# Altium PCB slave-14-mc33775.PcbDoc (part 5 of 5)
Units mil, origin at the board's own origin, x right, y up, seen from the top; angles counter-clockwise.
Board outline 6299.21 x 3937.01 mil, 6 copper layers (Top Copper, Supply, Signal Layer 1, Signal Layer 2, GND, Bot Copper), stack 69.773 mil thick; 428 components, 213 nets, 1149 pads, 1672 vias.
Unrouted connection lines stored in the file: 1.
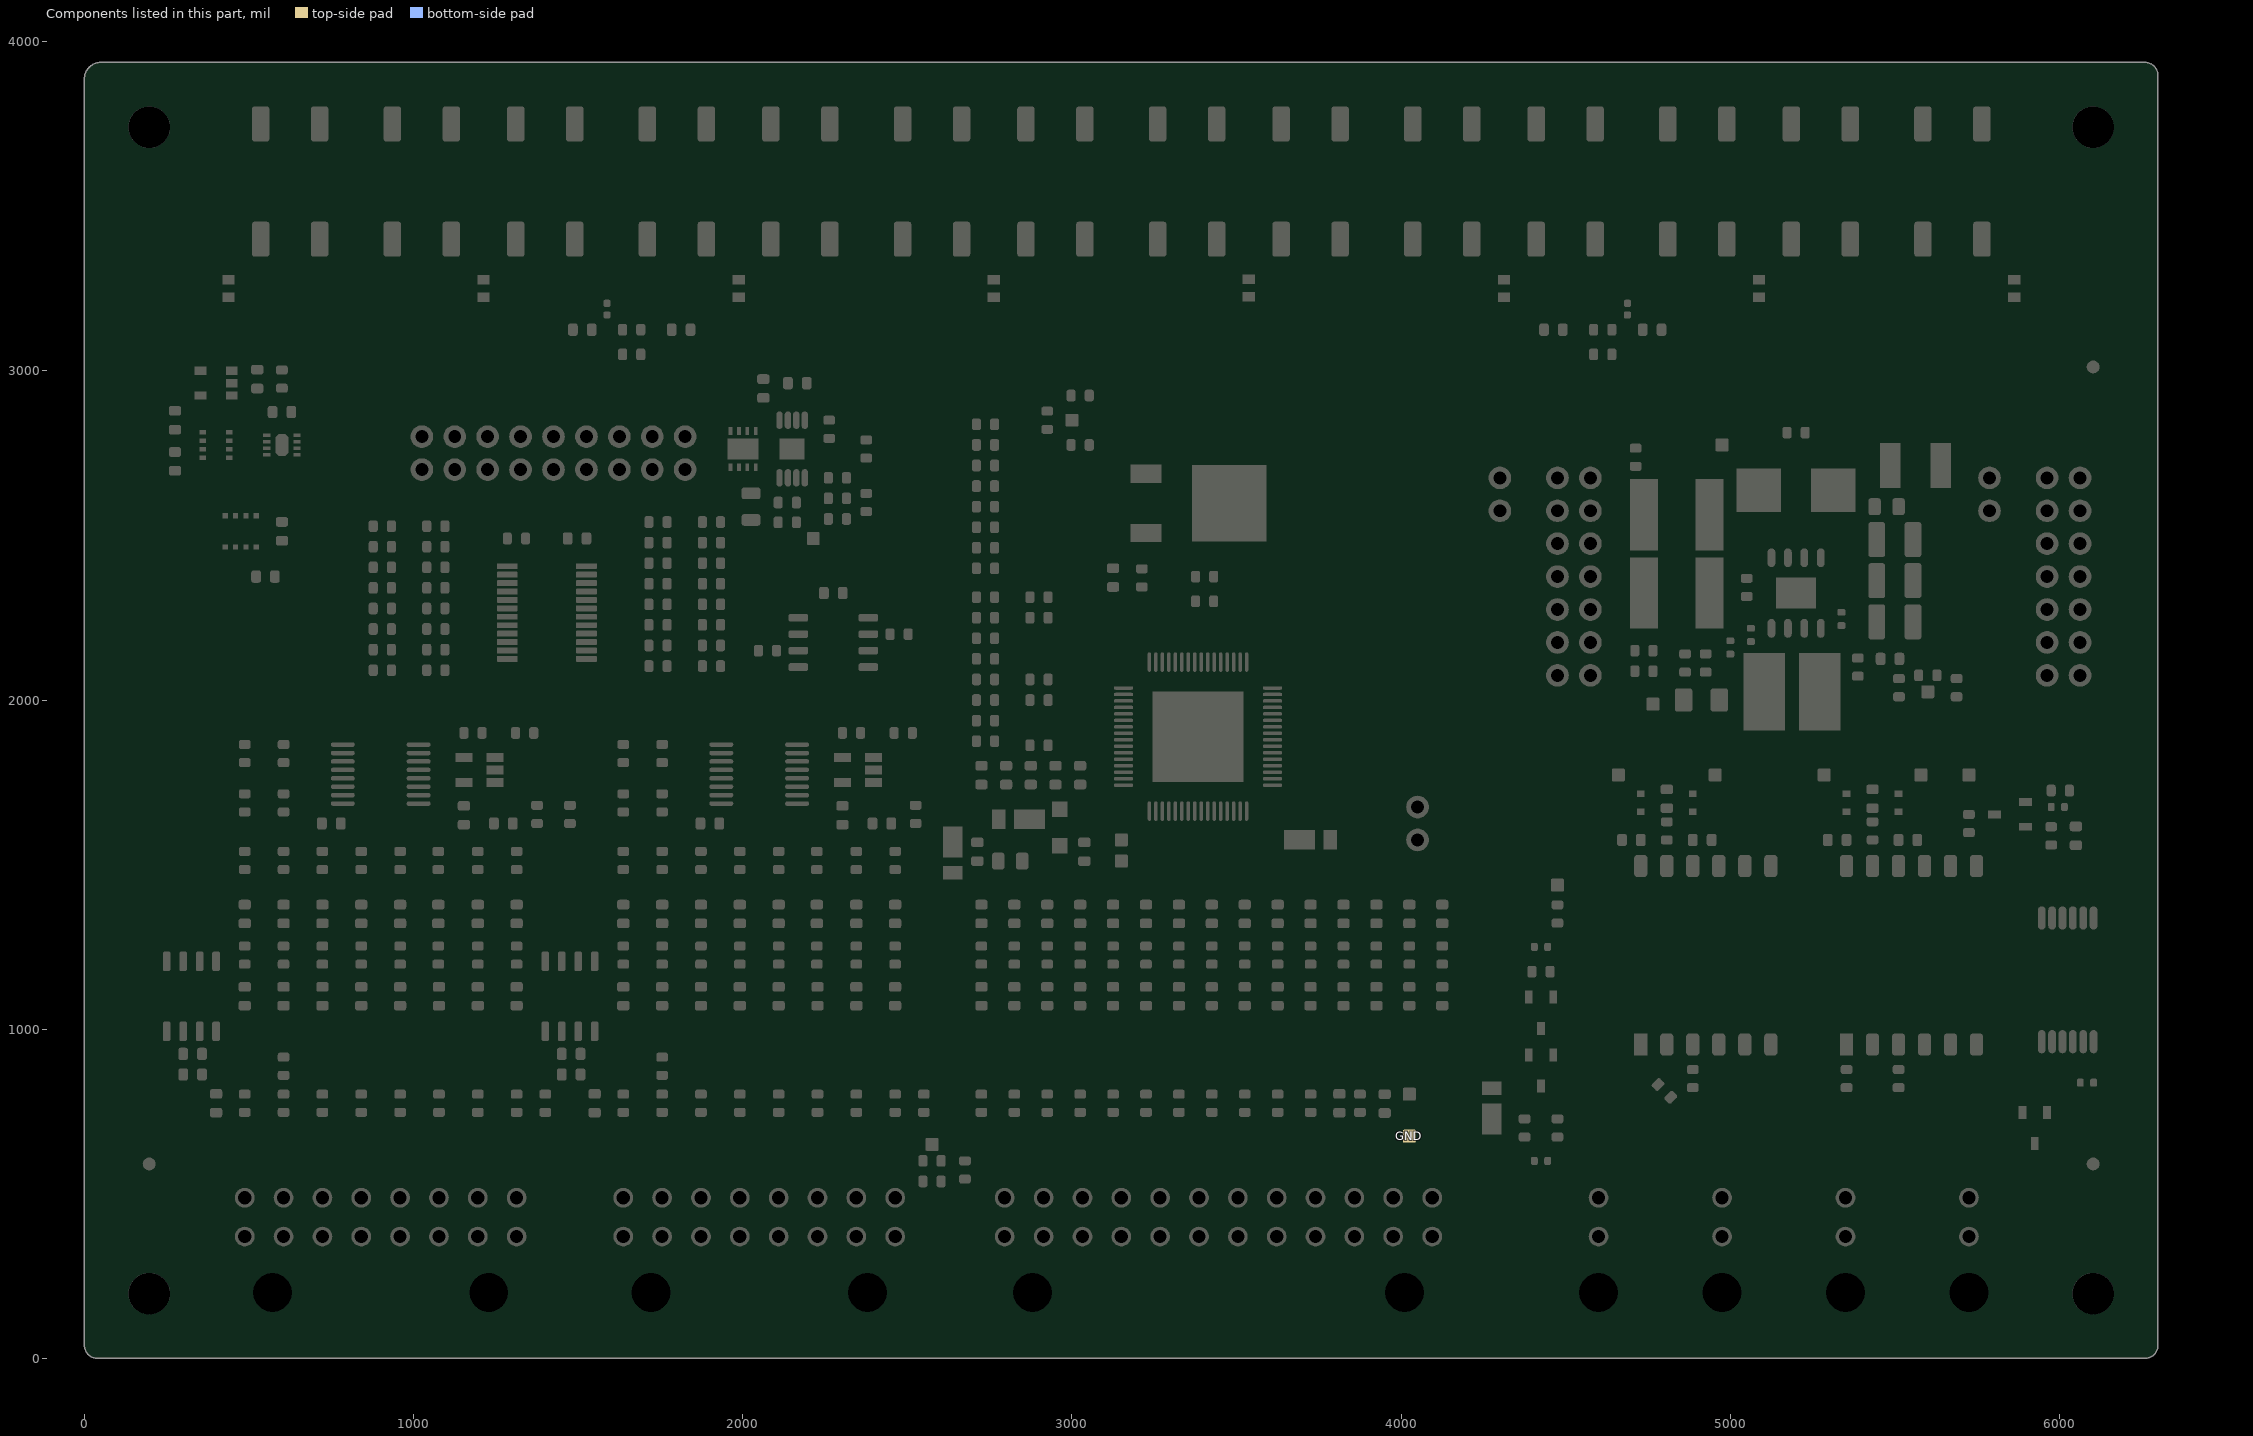
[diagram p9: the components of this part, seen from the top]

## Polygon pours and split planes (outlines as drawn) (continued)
no net on Top Overlay "Polygon_24_NoNet" (solid): 5467.42,2986.05 5468.17,2982.8 5470.88,2981.57 5473.58,2982.8 5474.34,2986.06 5474.34,3047.53 5498.56,2996.96 5500.45,2994.13 5503.43,2993.08 5506.4,2994.13 5508.29,2996.96 5532.51,3047.53 5532.51,2986.06 5533.27,2982.8 5535.97,2981.57 5538.69,2982.8 5539.44,2986.06 5539.44,3059.6 5539.13,3061.72 5538.22,3063.07 5535.75,3064.03 5533.45,3063.42 5531.48,3060.72 5503.43,3001.37 5475.39,3060.72 5473.42,3063.42 5471.12,3064.03 5468.65,3063.07 5467.74,3061.72 5467.43,3059.6 5467.41,2986.77 5467.4,2986.25
no net on Top Overlay "Polygon_22_NoNet" (solid): 5660.93,3062.77 5664.56,3062.13 5667.31,3060.36 5669.08,3057.62 5669.71,3054.03 5669.71,2991.35 5669.08,2987.72 5667.31,2984.98 5664.56,2983.21 5660.93,2982.57 5653.92,2981.15 5648.14,2977.25 5644.24,2971.48 5642.81,2964.45 5642.81,2951.01 5642.05,2947.42 5640.08,2944.66 5637.28,2942.89 5634.07,2942.26 5388.97,2942.26 5388.16,2932.83 5634.09,2932.83 5637.72,2933.2 5641.12,2934.27 5644.21,2935.95 5646.9,2938.17 5649.13,2940.86 5650.8,2943.94 5651.86,2947.34 5652.24,2950.98 5652.23,2964.39 5652.87,2968.02 5654.64,2970.76 5657.38,2972.53 5661,2973.16 5664.63,2973.53 5668.02,2974.6 5671.11,2976.27 5673.8,2978.49 5676.02,2981.18 5677.69,2984.26 5678.76,2987.66 5679.13,2991.3 5679.13,3054.05 5678.77,3057.73 5677.73,3061.17 5676.08,3064.26 5673.88,3066.92 5671.2,3069.13 5668.11,3070.78 5664.68,3071.81 5661.02,3072.17 5657.39,3072.85 5654.64,3074.7 5652.87,3077.48 5652.24,3080.91 5652.24,3094.36 5651.87,3097.99 5650.8,3101.4 5649.13,3104.49 5646.9,3107.18 5644.21,3109.39 5641.12,3111.07 5637.72,3112.13 5634.09,3112.5 5140.91,3112.5 5136.76,3112.17 5133.11,3111.2 5129.99,3109.63 5127.41,3107.5 5125.39,3104.86 5123.93,3101.76 5123.05,3098.24 5122.75,3094.36 5122.75,2950.98 5123.12,2947.34 5124.18,2943.94 5125.87,2940.86 5128.09,2938.17 5130.78,2935.95 5133.86,2934.27 5137.27,2933.2 5140.91,2932.83 5388.16,2932.83 5388.97,2942.26 5140.95,2942.25 5137.33,2942.89 5134.58,2944.66 5132.81,2947.4 5132.17,2950.99 5132.17,3094.31 5132.81,3097.93 5134.58,3100.68 5137.33,3102.45 5140.91,3103.08 5634.03,3103.09 5637.66,3102.45 5640.41,3100.68 5642.18,3097.93 5642.81,3094.35 5642.81,3080.88 5644.24,3073.86 5648.14,3068.09 5653.92,3064.19
no net on Top Overlay "Polygon_28_NoNet" (solid): 5174.17,2956.09 5164.45,2957.53 5163.81,2958.58 5165.43,2968.86 5165.87,2969.53 5166.43,2969.69 5166.75,2969.64 5172.29,2968.71 5176.38,2969.28 5179.35,2971.06 5181.39,2974.23 5182.67,2978.99 5192.65,3038.95 5192.43,3039.75 5191.67,3040.1 5182.61,3040.1 5181.86,3040.44 5181.64,3041.24 5183.42,3051.53 5184.32,3052.3 5193.91,3052.3 5194.94,3053.17 5195.82,3058.27 5197.01,3063.38 5198.82,3067.8 5201.25,3071.54 5204.31,3074.6 5207.99,3076.96 5212.32,3078.65 5222.83,3079.98 5229.9,3079.3 5235.54,3077.8 5236.13,3076.77 5234.36,3066.62 5233.87,3065.95 5233.37,3065.82 5232.98,3065.89 5229.08,3066.96 5224.3,3067.49 5219.19,3066.91 5215.6,3065.08 5213.23,3061.79 5211.87,3056.81 5211.27,3053.46 5211.48,3052.65 5212.24,3052.3 5226.68,3052.3 5227.42,3051.95 5227.65,3051.15 5225.87,3040.86 5224.96,3040.1 5209.98,3040.1 5208.95,3039.22 5198.72,2977.53 5195.91,2968.21 5193.66,2964.52 5190.85,2961.49 5187.5,2959.13 5183.58,2957.44 5174.38,2956.09
no net on Top Overlay "Polygon_26_NoNet" (solid): 5351.1,2981.27 5345.55,2981.89 5341.12,2983.94 5337.48,2987.7 5334.25,2993.39 5328.67,3005.36 5327.82,3005.96 5327.83,3005.96 5326.99,3005.53 5310.11,2982.63 5309.37,2982.25 5294.05,2982.25 5293.16,2982.8 5293.27,2983.86 5320.73,3018.66 5320.87,3019.74 5313.81,3035.52 5310.87,3039.73 5307.54,3040.65 5304.01,3040.38 5303.94,3040.38 5303.14,3040.68 5302.9,3041.51 5304.52,3051.36 5305.08,3052.08 5312.67,3053.41 5317.93,3052.88 5321.97,3051.05 5325.17,3047.63 5327.94,3042.37 5332.64,3031.38 5333.5,3030.75 5333.49,3030.75 5334.35,3031.21 5348.55,3051.9 5349.3,3052.3 5364.63,3052.3 5365.52,3051.74 5365.42,3050.69 5340.15,3017.88 5340.05,3016.77 5348.94,2998.91 5352.04,2994.66 5355.37,2993.74 5359.99,2994.28 5360.11,2994.29 5360.91,2994.03 5361.2,2993.16 5359.56,2983.45 5359.02,2982.75 5355.33,2981.63 5351.29,2981.29
no net on Top Overlay "Polygon_27_NoNet" (solid): 5264.04,3041.33 5259.29,3040.62 5255.34,3038.57 5252.02,3035.39 5249.34,3031.3 5247.26,3026.46 5245.79,3021.13 5244.63,3009.69 5245.5,3002.72 5248.02,2997.54 5252,2994.31 5258.32,2993.26 5257.21,2981.13 5249.28,2981.84 5243.15,2983.83 5238.16,2986.89 5234.24,2990.8 5231.32,2995.34 5229.32,3000.31 5228.18,3005.49 5227.82,3010.66 5228.41,3018.59 5230.18,3026.29 5233.1,3033.51 5237.19,3039.99 5242.41,3045.47 5248.77,3049.71 5256.23,3052.45 5264.78,3053.41 5272.07,3052.7 5278.17,3050.72 5283.13,3047.68 5287.04,3043.79 5289.94,3039.26 5291.93,3034.32 5293.06,3029.16 5293.43,3024.01 5292.83,3016.06 5291.07,3008.34 5288.16,3001.1 5284.09,2994.6 5278.88,2989.09 5272.56,2984.84 5265.13,2982.1 5260.95,2981.4 5259.06,2981.14 5257.22,2981.14 5258.32,2993.26 5259.65,2993.36 5261.94,2993.91 5265.91,2995.97 5269.23,2999.15 5271.91,3003.23 5274,3008.07 5275.46,3013.41 5276.63,3024.85 5275.75,3031.82 5273.24,3037 5269.25,3040.22
no net on Top Overlay "Polygon_1_NoNet" (solid): 350,1361.5 189.5,1361.5 189.5,2074 350,2074
VBAT_con_ext on Top Copper "VBAT_CON_EXT_L01_P148" (solid, remove dead copper, pour order 148): 2875,3112.5 2875,1925 4425,1925 4425,3112.5
GND on Top Copper "GND_L01_P139" (solid, remove dead copper, pour order 139): 1950,2950 2325,2950 2325,2412.5 2000,2412.5 2000,2612.5 1950,2662.5
GND on Top Copper "GND_L01_P147" (solid, remove dead copper, pour order 147): 4675,2825 5687.5,2825 5687.5,2075 5762.5,2000 5762.5,1950 4687.5,1950 4675,1937.5
SW on Top Copper "SW_L01_P145" (solid, pour order 145): 5212.5,2287.5 5212.5,1887.5 5387.5,1887.5 5412.5,1912.5 5412.5,2237.5 5362.5,2287.5
CIN0 on Top Copper "CIN0_L01_P019" (solid, pour order 19): 5687.5,3975 5687.5,3250 6299.21,3250 6299.21,3975
CIN14 on Top Copper "CIN14_L01_P018" (solid, pour order 18): 612.5,3975 612.5,3250 0,3250 0,3975
GND on Top Copper "GND_L01_P001" (solid, pour order 1): 250,3250 250,3150 2950,3150 2950,3250
+3.3V on Top Copper "+3.3V_L01_P146" (solid, pour order 146): 4962.5,2162.5 5175,2162.5 5175,1875 4925,1875 4925,2075 4950,2100 4950,2112.5 4937.5,2125 4900,2125 4900,2187.5 4937.5,2187.5
VBAT_con_ext_lim on Top Copper "VBAT_CON_EXT_LIM_L01_P140" (solid, pour order 140): 4675,2725 4775,2725 4800,2700 4800,2200 4675,2200
VBAT_con_ext_emi on Top Copper "VBAT_CON_EXT_EMI_L01_P141" (solid, pour order 141): 5225,2737.5 5412.5,2737.5 5425,2725 5425,2650 5462.5,2612.5 5462.5,2562.5 5487.5,2537.5 5487.5,2087.5 5412.5,2087.5 5412.5,2387.5 5312.5,2487.5 5225,2575
VBAT_con_ext_emi on Top Copper "VBAT_CON_EXT_EMI_L01_P142" (solid, pour order 142): 5225,2737.5 5212.5,2750 5212.5,2837.5 5312.5,2837.5 5412.5,2737.5
VBAT_con_ext_lim on Top Copper "VBAT_CON_EXT_LIM_L01_P144" (solid, pour order 144): 4800,2637.5 4837.5,2675 4975,2675 4975,2562.5 5162.5,2562.5 5175,2575 5175,2737.5 5187.5,2750 5187.5,2837.5 5100,2837.5 5012.5,2750 4800,2750 4775,2725
GND on Top Copper "GND_L01_P138" (solid, pour order 138): -37.5,3112.5 812.5,3112.5 812.5,2187.5 -50,2187.5
CIN8 on Top Copper "CIN8_L01_P110" (solid, pour order 110): 2587.5,3975 2937.5,3975 2937.5,3250 2587.5,3250
CIN10 on Top Copper "CIN10_L01_P043" (solid, pour order 43): 1812.5,3975 2162.5,3975 2162.5,3250 1812.5,3250
CIN2 on Top Copper "CIN2_L01_P025" (solid, pour order 25): 4912.5,3975 5262.5,3975 5262.5,3250 4912.5,3250
CIN4 on Top Copper "CIN4_L01_P024" (solid, pour order 24): 4137.5,3975 4487.5,3975 4487.5,3250 4137.5,3250
CIN6 on Top Copper "CIN6_L02_P023" (solid, pour order 23): 3362.5,3975 3712.5,3975 3712.5,3250 3362.5,3250
CIN12 on Top Copper "CIN12_L01_P020" (solid, pour order 20): 1037.5,3975 1387.5,3975 1387.5,3250 1037.5,3250
BAL.CB_LO0 on Top Copper "BAL.CB_LO0_L01_P017" (solid, pour order 17): 5662.5,3975 5487.5,3975 5487.5,3250 5662.5,3250
BAL.CB_LO2 on Top Copper "BAL.CB_LO2_L01_P016" (solid, pour order 16): 4887.5,3975 4712.5,3975 4712.5,3250 4887.5,3250
BAL.CB_LO4 on Top Copper "BAL.CB_LO4_L01_P015" (solid, pour order 15): 4112.5,3975 3937.5,3975 3937.5,3250 4112.5,3250
BAL.CB_LO6 on Top Copper "BAL.CB_LO6_L01_P014" (solid, pour order 14): 3337.5,3975 3162.5,3975 3162.5,3250 3337.5,3250
BAL.CB_LO8 on Top Copper "BAL.CB_LO8_L01_P013" (solid, pour order 13): 2562.5,3975 2387.5,3975 2387.5,3250 2562.5,3250
BAL.CB_LO10 on Top Copper "BAL.CB_LO10_L01_P012" (solid, pour order 12): 1787.5,3975 1612.5,3975 1612.5,3250 1787.5,3250
BAL.CB_LO12 on Top Copper "BAL.CB_LO12_L01_P011" (solid, pour order 11): 1012.5,3975 837.5,3975 837.5,3250 1012.5,3250
BAL.CB_HI2 on Top Copper "BAL.CB_HI2_L01_P010" (solid, pour order 10): 5287.5,3975 5462.5,3975 5462.5,3250 5287.5,3250
BAL.CB_HI4 on Top Copper "BAL.CB_HI4_L01_P009" (solid, pour order 9): 4512.5,3975 4687.5,3975 4687.5,3250 4512.5,3250
BAL.CB_HI6 on Top Copper "BAL.CB_HI6_L01_P008" (solid, pour order 8): 3737.5,3975 3912.5,3975 3912.5,3250 3737.5,3250
BAL.CB_HI8 on Top Copper "BAL.CB_HI8_L01_P007" (solid, pour order 7): 2962.5,3975 3137.5,3975 3137.5,3250 2962.5,3250
BAL.CB_HI10 on Top Copper "BAL.CB_HI10_L01_P006" (solid, pour order 6): 2187.5,3975 2362.5,3975 2362.5,3250 2187.5,3250
BAL.CB_HI12 on Top Copper "BAL.CB_HI12_L01_P005" (solid, pour order 5): 1412.5,3975 1587.5,3975 1587.5,3250 1412.5,3250
BAL.CB_HI14 on Top Copper "BAL.CB_HI14_L01_P004" (solid, pour order 4): 637.5,3975 812.5,3975 812.5,3250 637.5,3250
GND on Top Copper "GND_L01_P002" (solid, pour order 2): 3350,3250 3350,3150 6050,3150 6050,3250
GND on GND "GND_L05_P000" (solid, remove dead copper, pour order 0): -199.38,3250 6587.5,3250 6587.5,-125 6500,-212.5 -250,-212.5
CIN0 on GND "CIN0_L05_P107" (solid, pour order 107): 5687.5,3975 5687.5,3250 6299.21,3250 6299.21,3975
CIN14 on GND "CIN14_L05_P106" (solid, pour order 106): 612.5,3975 612.5,3250 0,3250 0,3975
CIN10 on GND "CIN10_L05_P131" (solid, pour order 131): 1812.5,3975 2162.5,3975 2162.5,3250 1812.5,3250
BAL.CB_HI2 on GND "BAL.CB_HI2_L05_P120" (solid, pour order 120): 5287.5,3975 5462.5,3975 5462.5,3250 5287.5,3250
BAL.CB_HI4 on GND "BAL.CB_HI4_L05_P119" (solid, pour order 119): 4512.5,3975 4687.5,3975 4687.5,3250 4512.5,3250
BAL.CB_HI10 on GND "BAL.CB_HI10_L05_P116" (solid, pour order 116): 2187.5,3975 2362.5,3975 2362.5,3250 2187.5,3250
BAL.CB_HI12 on GND "BAL.CB_HI12_L05_P115" (solid, pour order 115): 1412.5,3975 1587.5,3975 1587.5,3250 1412.5,3250
BAL.CB_HI14 on GND "BAL.CB_HI14_L05_P114" (solid, pour order 114): 637.5,3975 812.5,3975 812.5,3250 637.5,3250
CIN2 on GND "CIN2_L05_P113" (solid, pour order 113): 4912.5,3975 5262.5,3975 5262.5,3250 4912.5,3250
CIN4 on GND "CIN4_L05_P112" (solid, pour order 112): 4137.5,3975 4487.5,3975 4487.5,3250 4137.5,3250
CIN12 on GND "CIN12_L05_P108" (solid, pour order 108): 1037.5,3975 1387.5,3975 1387.5,3250 1037.5,3250
BAL.CB_LO2 on GND "BAL.CB_LO2_L05_P104" (solid, pour order 104): 4887.5,3975 4712.5,3975 4712.5,3250 4887.5,3250
BAL.CB_LO4 on GND "BAL.CB_LO4_L05_P103" (solid, pour order 103): 4112.5,3975 3937.5,3975 3937.5,3250 4112.5,3250
BAL.CB_LO6 on GND "BAL.CB_LO6_L05_P102" (solid, pour order 102): 3337.5,3975 3162.5,3975 3162.5,3250 3337.5,3250
BAL.CB_LO8 on GND "BAL.CB_LO8_L05_P101" (solid, pour order 101): 2562.5,3975 2387.5,3975 2387.5,3250 2562.5,3250
BAL.CB_LO12 on GND "BAL.CB_LO12_L05_P099" (solid, pour order 99): 1012.5,3975 837.5,3975 837.5,3250 1012.5,3250
BAL.CB_HI6 on GND "BAL.CB_HI6_L05_P096" (solid, pour order 96): 3737.5,3975 3912.5,3975 3912.5,3250 3737.5,3250
BAL.CB_HI8 on GND "BAL.CB_HI8_L05_P095" (solid, pour order 95): 2962.5,3975 3137.5,3975 3137.5,3250 2962.5,3250
CIN6 on GND "CIN6_L05_P089" (solid, pour order 89): 3362.5,3975 3712.5,3975 3712.5,3250 3362.5,3250
CIN8 on GND "CIN8_L05_P088" (solid, pour order 88): 2587.5,3975 2937.5,3975 2937.5,3250 2587.5,3250
BAL.CB_LO0 on GND "BAL.CB_LO0_L05_P061" (solid, pour order 61): 5662.5,3975 5487.5,3975 5487.5,3250 5662.5,3250
BAL.CB_LO10 on GND "BAL.CB_LO10_L05_P056" (solid, pour order 56): 1787.5,3975 1612.5,3975 1612.5,3250 1787.5,3250
VDDIO on Supply "VDDIO_L02_P137" (solid, remove dead copper, pour order 137): -25,3250 6325,3250 6325,-50 -25,-50
VDDC on Supply "VDDC_L02_P136" (solid, pour order 136): 4250,-50 4250,3250 6400,3250 6400,-50
CIN0 on Supply "CIN0_L02_P041" (solid, pour order 41): 5687.5,3975 5687.5,3250 6299.21,3250 6299.21,3975
CIN14 on Supply "CIN14_L02_P040" (solid, pour order 40): 612.5,3975 612.5,3250 0,3250 0,3975
CIN6 on Supply "CIN6_L02_P023" (solid, pour order 111): 3362.5,3975 3712.5,3975 3712.5,3250 3362.5,3250
BAL.CB_HI8 on Supply "BAL.CB_HI8_L02_P073" (solid, pour order 73): 2962.5,3975 3137.5,3975 3137.5,3250 2962.5,3250
CIN8 on Supply "CIN8_L02_P044" (solid, pour order 44): 2587.5,3975 2937.5,3975 2937.5,3250 2587.5,3250
CIN2 on Supply "CIN2_L02_P047" (solid, pour order 47): 4912.5,3975 5262.5,3975 5262.5,3250 4912.5,3250
CIN4 on Supply "CIN4_L02_P046" (solid, pour order 46): 4137.5,3975 4487.5,3975 4487.5,3250 4137.5,3250
CIN10 on Supply "CIN10_L02_P021" (solid, pour order 21): 1812.5,3975 2162.5,3975 2162.5,3250 1812.5,3250
CIN12 on Supply "CIN12_L02_P042" (solid, pour order 42): 1037.5,3975 1387.5,3975 1387.5,3250 1037.5,3250
BAL.CB_LO0 on Supply "BAL.CB_LO0_L02_P039" (solid, pour order 39): 5662.5,3975 5487.5,3975 5487.5,3250 5662.5,3250
BAL.CB_LO2 on Supply "BAL.CB_LO2_L02_P038" (solid, pour order 38): 4887.5,3975 4712.5,3975 4712.5,3250 4887.5,3250
BAL.CB_LO4 on Supply "BAL.CB_LO4_L02_P037" (solid, pour order 37): 4112.5,3975 3937.5,3975 3937.5,3250 4112.5,3250
BAL.CB_LO6 on Supply "BAL.CB_LO6_L02_P036" (solid, pour order 36): 3337.5,3975 3162.5,3975 3162.5,3250 3337.5,3250
BAL.CB_LO8 on Supply "BAL.CB_LO8_L02_P035" (solid, pour order 35): 2562.5,3975 2387.5,3975 2387.5,3250 2562.5,3250
BAL.CB_LO10 on Supply "BAL.CB_LO10_L02_P034" (solid, pour order 34): 1787.5,3975 1612.5,3975 1612.5,3250 1787.5,3250
BAL.CB_LO12 on Supply "BAL.CB_LO12_L02_P033" (solid, pour order 33): 1012.5,3975 837.5,3975 837.5,3250 1012.5,3250
BAL.CB_HI2 on Supply "BAL.CB_HI2_L02_P032" (solid, pour order 32): 5287.5,3975 5462.5,3975 5462.5,3250 5287.5,3250
BAL.CB_HI4 on Supply "BAL.CB_HI4_L02_P030" (solid, pour order 30): 4512.5,3975 4687.5,3975 4687.5,3250 4512.5,3250
BAL.CB_HI6 on Supply "BAL.CB_HI6_L02_P031" (solid, pour order 31): 3737.5,3975 3912.5,3975 3912.5,3250 3737.5,3250
BAL.CB_HI10 on Supply "BAL.CB_HI10_L02_P028" (solid, pour order 28): 2187.5,3975 2362.5,3975 2362.5,3250 2187.5,3250
BAL.CB_HI12 on Supply "BAL.CB_HI12_L02_P027" (solid, pour order 27): 1412.5,3975 1587.5,3975 1587.5,3250 1412.5,3250
BAL.CB_HI14 on Supply "BAL.CB_HI14_L02_P026" (solid, pour order 26): 637.5,3975 812.5,3975 812.5,3250 637.5,3250
CIN0 on Bot Copper "CIN0_L06_P129" (solid, pour order 129): 5687.5,3975 5687.5,3250 6299.21,3250 6299.21,3975
CIN14 on Bot Copper "CIN14_L06_P128" (solid, pour order 128): 612.5,3975 612.5,3250 0,3250 0,3975
BAL.CB_HI6 on Bot Copper "BAL.CB_HI6_L06_P118" (solid, pour order 118): 3737.5,3975 3912.5,3975 3912.5,3250 3737.5,3250
BAL.CB_HI2 on Bot Copper "BAL.CB_HI2_L06_P098" (solid, pour order 98): 5287.5,3975 5462.5,3975 5462.5,3250 5287.5,3250
BAL.CB_HI10 on Bot Copper "BAL.CB_HI10_L06_P094" (solid, pour order 94): 2187.5,3975 2362.5,3975 2362.5,3250 2187.5,3250
BAL.CB_HI12 on Bot Copper "BAL.CB_HI12_L06_P093" (solid, pour order 93): 1412.5,3975 1587.5,3975 1587.5,3250 1412.5,3250
CIN10 on Bot Copper "CIN10_L06_P087" (solid, pour order 87): 1812.5,3975 2162.5,3975 2162.5,3250 1812.5,3250
BAL.CB_HI4 on Bot Copper "BAL.CB_HI4_L06_P053" (solid, pour order 53): 4512.5,3975 4687.5,3975 4687.5,3250 4512.5,3250
BAL.CB_HI8 on Bot Copper "BAL.CB_HI8_L06_P051" (solid, pour order 51): 2962.5,3975 3137.5,3975 3137.5,3250 2962.5,3250
BAL.CB_HI14 on Bot Copper "BAL.CB_HI14_L06_P048" (solid, pour order 48): 637.5,3975 812.5,3975 812.5,3250 637.5,3250
CIN8 on Bot Copper "CIN8_L06_P066" (solid, pour order 66): 2587.5,3975 2937.5,3975 2937.5,3250 2587.5,3250
CIN2 on Bot Copper "CIN2_L06_P135" (solid, pour order 135): 4912.5,3975 5262.5,3975 5262.5,3250 4912.5,3250
CIN4 on Bot Copper "CIN4_L06_P134" (solid, pour order 134): 4137.5,3975 4487.5,3975 4487.5,3250 4137.5,3250
CIN6 on Bot Copper "CIN6_L06_P133" (solid, pour order 133): 3362.5,3975 3712.5,3975 3712.5,3250 3362.5,3250
CIN12 on Bot Copper "CIN12_L06_P130" (solid, pour order 130): 1037.5,3975 1387.5,3975 1387.5,3250 1037.5,3250
BAL.CB_LO0 on Bot Copper "BAL.CB_LO0_L06_P127" (solid, pour order 127): 5662.5,3975 5487.5,3975 5487.5,3250 5662.5,3250
BAL.CB_LO2 on Bot Copper "BAL.CB_LO2_L06_P126" (solid, pour order 126): 4887.5,3975 4712.5,3975 4712.5,3250 4887.5,3250
BAL.CB_LO4 on Bot Copper "BAL.CB_LO4_L06_P125" (solid, pour order 125): 4112.5,3975 3937.5,3975 3937.5,3250 4112.5,3250
BAL.CB_LO6 on Bot Copper "BAL.CB_LO6_L06_P124" (solid, pour order 124): 3337.5,3975 3162.5,3975 3162.5,3250 3337.5,3250
BAL.CB_LO8 on Bot Copper "BAL.CB_LO8_L06_P123" (solid, pour order 123): 2562.5,3975 2387.5,3975 2387.5,3250 2562.5,3250
BAL.CB_LO10 on Bot Copper "BAL.CB_LO10_L06_P122" (solid, pour order 122): 1787.5,3975 1612.5,3975 1612.5,3250 1787.5,3250
BAL.CB_LO12 on Bot Copper "BAL.CB_LO12_L06_P121" (solid, pour order 121): 1012.5,3975 837.5,3975 837.5,3250 1012.5,3250
CIN0 on Signal Layer 1 "CIN0_L03_P063" (solid, pour order 63): 5687.5,3975 5687.5,3250 6299.21,3250 6299.21,3975
CIN14 on Signal Layer 1 "CIN14_L03_P062" (solid, pour order 62): 612.5,3975 612.5,3250 0,3250 0,3975
CIN8 on Signal Layer 1 "CIN8_L03_P022" (solid, pour order 22): 2587.5,3975 2937.5,3975 2937.5,3250 2587.5,3250
BAL.CB_HI8 on Signal Layer 1 "BAL.CB_HI8_L03_P117" (solid, pour order 117): 2962.5,3975 3137.5,3975 3137.5,3250 2962.5,3250
CIN4 on Signal Layer 1 "CIN4_L03_P090" (solid, pour order 90): 4137.5,3975 4487.5,3975 4487.5,3250 4137.5,3250
BAL.CB_LO0 on Signal Layer 1 "BAL.CB_LO0_L03_P083" (solid, pour order 83): 5662.5,3975 5487.5,3975 5487.5,3250 5662.5,3250
BAL.CB_LO4 on Signal Layer 1 "BAL.CB_LO4_L03_P081" (solid, pour order 81): 4112.5,3975 3937.5,3975 3937.5,3250 4112.5,3250
BAL.CB_LO10 on Signal Layer 1 "BAL.CB_LO10_L03_P078" (solid, pour order 78): 1787.5,3975 1612.5,3975 1612.5,3250 1787.5,3250
BAL.CB_HI4 on Signal Layer 1 "BAL.CB_HI4_L03_P075" (solid, pour order 75): 4512.5,3975 4687.5,3975 4687.5,3250 4512.5,3250
BAL.CB_HI6 on Signal Layer 1 "BAL.CB_HI6_L03_P074" (solid, pour order 74): 3737.5,3975 3912.5,3975 3912.5,3250 3737.5,3250
BAL.CB_HI14 on Signal Layer 1 "BAL.CB_HI14_L03_P070" (solid, pour order 70): 637.5,3975 812.5,3975 812.5,3250 637.5,3250
CIN10 on Signal Layer 1 "CIN10_L03_P065" (solid, pour order 65): 1812.5,3975 2162.5,3975 2162.5,3250 1812.5,3250
CIN6 on Signal Layer 1 "CIN6_L02_P023" (solid, pour order 67): 3362.5,3975 3712.5,3975 3712.5,3250 3362.5,3250
CIN12 on Signal Layer 1 "CIN12_L03_P064" (solid, pour order 64): 1037.5,3975 1387.5,3975 1387.5,3250 1037.5,3250
CIN2 on Signal Layer 1 "CIN2_L03_P069" (solid, pour order 69): 4912.5,3975 5262.5,3975 5262.5,3250 4912.5,3250
BAL.CB_LO2 on Signal Layer 1 "BAL.CB_LO2_L03_P060" (solid, pour order 60): 4887.5,3975 4712.5,3975 4712.5,3250 4887.5,3250
BAL.CB_LO6 on Signal Layer 1 "BAL.CB_LO6_L03_P058" (solid, pour order 58): 3337.5,3975 3162.5,3975 3162.5,3250 3337.5,3250
BAL.CB_LO8 on Signal Layer 1 "BAL.CB_LO8_L03_P057" (solid, pour order 57): 2562.5,3975 2387.5,3975 2387.5,3250 2562.5,3250
BAL.CB_LO12 on Signal Layer 1 "BAL.CB_LO12_L03_P055" (solid, pour order 55): 1012.5,3975 837.5,3975 837.5,3250 1012.5,3250
BAL.CB_HI2 on Signal Layer 1 "BAL.CB_HI2_L03_P054" (solid, pour order 54): 5287.5,3975 5462.5,3975 5462.5,3250 5287.5,3250
BAL.CB_HI10 on Signal Layer 1 "BAL.CB_HI10_L03_P050" (solid, pour order 50): 2187.5,3975 2362.5,3975 2362.5,3250 2187.5,3250
BAL.CB_HI12 on Signal Layer 1 "BAL.CB_HI12_L03_P049" (solid, pour order 49): 1412.5,3975 1587.5,3975 1587.5,3250 1412.5,3250
CIN0 on Signal Layer 2 "CIN0_L04_P085" (solid, pour order 85): 5687.5,3975 5687.5,3250 6299.21,3250 6299.21,3975
CIN14 on Signal Layer 2 "CIN14_L04_P084" (solid, pour order 84): 612.5,3975 612.5,3250 0,3250 0,3975
CIN6 on Signal Layer 2 "CIN6_L04_P045" (solid, pour order 45): 3362.5,3975 3712.5,3975 3712.5,3250 3362.5,3250
CIN8 on Signal Layer 2 "CIN8_L04_P132" (solid, pour order 132): 2587.5,3975 2937.5,3975 2937.5,3250 2587.5,3250
CIN10 on Signal Layer 2 "CIN10_L04_P109" (solid, pour order 109): 1812.5,3975 2162.5,3975 2162.5,3250 1812.5,3250
BAL.CB_LO0 on Signal Layer 2 "BAL.CB_LO0_L04_P105" (solid, pour order 105): 5662.5,3975 5487.5,3975 5487.5,3250 5662.5,3250
BAL.CB_LO10 on Signal Layer 2 "BAL.CB_LO10_L04_P100" (solid, pour order 100): 1787.5,3975 1612.5,3975 1612.5,3250 1787.5,3250
BAL.CB_HI14 on Signal Layer 2 "BAL.CB_HI14_L04_P092" (solid, pour order 92): 637.5,3975 812.5,3975 812.5,3250 637.5,3250
CIN2 on Signal Layer 2 "CIN2_L04_P091" (solid, pour order 91): 4912.5,3975 5262.5,3975 5262.5,3250 4912.5,3250
CIN12 on Signal Layer 2 "CIN12_L04_P086" (solid, pour order 86): 1037.5,3975 1387.5,3975 1387.5,3250 1037.5,3250
BAL.CB_LO2 on Signal Layer 2 "BAL.CB_LO2_L04_P082" (solid, pour order 82): 4887.5,3975 4712.5,3975 4712.5,3250 4887.5,3250
BAL.CB_LO6 on Signal Layer 2 "BAL.CB_LO6_L04_P080" (solid, pour order 80): 3337.5,3975 3162.5,3975 3162.5,3250 3337.5,3250
BAL.CB_LO8 on Signal Layer 2 "BAL.CB_LO8_L04_P079" (solid, pour order 79): 2562.5,3975 2387.5,3975 2387.5,3250 2562.5,3250
BAL.CB_LO12 on Signal Layer 2 "BAL.CB_LO12_L04_P077" (solid, pour order 77): 1012.5,3975 837.5,3975 837.5,3250 1012.5,3250
BAL.CB_HI10 on Signal Layer 2 "BAL.CB_HI10_L04_P072" (solid, pour order 72): 2187.5,3975 2362.5,3975 2362.5,3250 2187.5,3250
BAL.CB_HI12 on Signal Layer 2 "BAL.CB_HI12_L04_P071" (solid, pour order 71): 1412.5,3975 1587.5,3975 1587.5,3250 1412.5,3250
BAL.CB_HI4 on Signal Layer 2 "BAL.CB_HI4_L04_P097" (solid, pour order 97): 4512.5,3975 4687.5,3975 4687.5,3250 4512.5,3250
BAL.CB_HI2 on Signal Layer 2 "BAL.CB_HI2_L04_P076" (solid, pour order 76): 5287.5,3975 5462.5,3975 5462.5,3250 5287.5,3250
BAL.CB_HI8 on Signal Layer 2 "BAL.CB_HI8_L04_P029" (solid, pour order 29): 2962.5,3975 3137.5,3975 3137.5,3250 2962.5,3250
CIN4 on Signal Layer 2 "CIN4_L04_P068" (solid, pour order 68): 4137.5,3975 4487.5,3975 4487.5,3250 4137.5,3250
BAL.CB_LO4 on Signal Layer 2 "BAL.CB_LO4_L04_P059" (solid, pour order 59): 4112.5,3975 3937.5,3975 3937.5,3250 4112.5,3250
BAL.CB_HI6 on Signal Layer 2 "BAL.CB_HI6_L04_P052" (solid, pour order 52): 3737.5,3975 3912.5,3975 3912.5,3250 3737.5,3250

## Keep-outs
Keep-Out Layer:
  circle w228.35: c196.85,196.85 r185.04
  circle w228.35: c6102.36,196.85 r185.04
  circle w228.35: c196.85,3740.16 r185.04
  circle w228.35: c6102.36,3740.16 r185.04

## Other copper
Top Copper:
  pour cut-out: 3987.5,1737.5 4112.5,1737.5 4112.5,1512.5 3987.5,1512.5
  pour cut-out: 5725,2737.5 5850,2737.5 5850,2512.5 5725,2512.5
  pour cut-out: 4237.5,2737.5 4362.5,2737.5 4362.5,2512.5 4237.5,2512.5
  pour cut-out: 362.5,2625 700,2625 700,2300 687.5,2287.5 362.5,2287.5
  text "TOP (1)" at 6244.68,3056.1 h40 r90
Signal Layer 1:
  pour cut-out: 3987.5,1737.5 4112.5,1737.5 4112.5,1512.5 3987.5,1512.5
  pour cut-out: 5725,2737.5 5850,2737.5 5850,2512.5 5725,2512.5
  pour cut-out: 4237.5,2737.5 4362.5,2737.5 4362.5,2512.5 4237.5,2512.5
  text "3" at 6244.68,3056.1 h40 r90
Signal Layer 2:
  pour cut-out: 3987.5,1737.5 4112.5,1737.5 4112.5,1512.5 3987.5,1512.5
  pour cut-out: 5725,2737.5 5850,2737.5 5850,2512.5 5725,2512.5
  pour cut-out: 4237.5,2737.5 4362.5,2737.5 4362.5,2512.5 4237.5,2512.5
  text "4" at 6244.69,3193.9 h40 r90
Supply:
  pour cut-out: 3987.5,1737.5 4112.5,1737.5 4112.5,1512.5 3987.5,1512.5
  pour cut-out: 5725,2737.5 5850,2737.5 5850,2512.5 5725,2512.5
  pour cut-out: 4237.5,2737.5 4362.5,2737.5 4362.5,2512.5 4237.5,2512.5
  pour cut-out: 4603.33,1516.81 4607.64,1516.81 4628.33,1537.5 6337.5,1537.5 6450,1425 6450,-50 4787.5,-50 4790.83,-46.67 4787.5,662.5 4607.64,825
  pour cut-out: 362.5,2625 700,2625 700,2300 687.5,2287.5 362.5,2287.5
  pour cut-out: 6350,1300 5900,1300 5900,1500 6050,1500 6350,1800 6450,1800 6450,1675 6350,1575
  pour cut-out: 4825,150 4800,500 4475,175 4350,50 4350,-50 4800,-50 4825,-25
  text "2" at 6244.68,3056.1 h40 r90
GND:
  pour cut-out: 3987.5,1737.5 4112.5,1737.5 4112.5,1512.5 3987.5,1512.5
  pour cut-out: 5725,2737.5 5850,2737.5 5850,2512.5 5725,2512.5
  pour cut-out: 4237.5,2737.5 4362.5,2737.5 4362.5,2512.5 4237.5,2512.5
  pour cut-out: 4603.33,1516.81 4607.64,1516.81 4628.33,1537.5 6337.5,1537.5 6450,1425 6450,-50 4787.5,-50 4790.83,-46.67 4787.5,662.5 4607.64,825
  pour cut-out: 4825,150 4800,500 4475,175 4350,50 4350,-50 4800,-50 4825,-25
  pour cut-out: 6350,1300 5900,1300 5900,1500 6050,1500 6350,1800 6450,1800 6450,1675 6350,1575
  pour cut-out: 362.5,2625 700,2625 700,2300 687.5,2287.5 362.5,2287.5
  text "5" at 6244.69,3193.9 h40 r90
Bot Copper:
  pour cut-out: 3987.5,1737.5 4112.5,1737.5 4112.5,1512.5 3987.5,1512.5
  pour cut-out: 5725,2737.5 5850,2737.5 5850,2512.5 5725,2512.5
  pour cut-out: 4237.5,2737.5 4362.5,2737.5 4362.5,2512.5 4237.5,2512.5
  text "BOT (6)" at 6244.69,3193.9 h40 r90

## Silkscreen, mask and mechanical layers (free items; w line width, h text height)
Top Overlay:
  drawing of 11 lines, arcs and shapes, not listed
  text "Passive Balancing" at 2693.42,3548.33 h118.11
  text "MCP9800" at 212.8,2885.14 h40 r90
  text "SHT35" at 775.3,2708.04 h40 r90
  text "BME280" at 212.64,2707.63 h40 r90
  text "↯" at 3787.5,2700 h1200
  text "HIGH" at 1700.4,2587.2 h40
  text "LOW" at 1864.61,2587.2 h40
  text "LOW" at 864.61,2574.7 h40
  text "HIGH" at 1025.4,2574.7 h40
  text "DANGER / high voltage / may be present" at 3637.36,2529.74 h60
  text "15" at 1805.76,2528.11 h40
  text "0" at 977.86,2515.61 h40
  text "14" at 1805.62,2465.38 h40
  text "1" at 980.56,2452.88 h40
  text "BME680" at 557.63,2412.36 h40
  text "13" at 1805.97,2403.11 h40
  text "2" at 977.58,2390.38 h40
  text "12" at 1806.11,2340.38 h40
  text "3" at 977.66,2328.11 h40
  text "11" at 1808.12,2277.88 h40
  text "4" at 976.98,2265.39 h40
  text "10" at 1806.09,2215.61 h40
  text "5" at 977.58,2203.34 h40
  text "9" at 1815.13,2153.11 h40
  text "6" at 977.63,2140.61 h40
  text "8" at 1815.25,2090.61 h40
  text "7" at 977.8,2078.11 h40
  text "foxBMS" at 3775,1950 h150
  text "Fraunhofer IISB / '.GlobalProject' v'.Global_Major_Minor_Patch_Version'" at 177,1361.5 h60 r90
  text "CT1" at 3987.82,1291.44 h40 r90
  text "CT9" at 3187.8,1289.36 h40 r90
  text "CT8" at 3287.8,1289.32 h40 r90
  text "CT7" at 3387.82,1289.32 h40 r90
  text "CT6" at 3487.8,1289.16 h40 r90
  text "CT5" at 3587.8,1289.07 h40 r90
  text "CT4" at 3687.82,1288.94 h40 r90
  text "CT3" at 3787.8,1289.29 h40 r90
  text "CT2" at 3887.82,1289.42 h40 r90
  text "CT0" at 4087.8,1289.41 h40 r90
  text "CT11" at 2987.82,1281.5 h40 r90
  text "CT14" at 2687.82,1279 h40 r90
  text "CT13" at 2787.8,1279.35 h40 r90
  text "CT12" at 2887.82,1279.48 h40 r90
  text "CT10" at 3087.8,1279.47 h40 r90
  text "Input Filter" at 3125,920.96 h118.11
  text "Select Vmodule with 0R" at 2923.32,668.27 h60
  text "Temperature Measurement" at 801.55,622.64 h118.11
  text "Alarm / out" at 4525.66,594.9 h60
  text "Alarm / in" at 5675.66,594.88 h60
  text "TPL / low" at 4865.03,587.26 h60
  text "TPL / high" at 5240.03,587.26 h60
Bottom Overlay:
  text "DIO3" at 1234.97,2874.76 h40
  text "DIO7" at 1434.97,2874.76 h40
  text "DIO11" at 1634.97,2874.76 h40
  text "DIO15" at 1834.97,2874.76 h40
  text "DIO1" at 1134.98,2836.77 h40
  text "DIO5" at 1334.97,2836.77 h40
  text "DIO9" at 1534.97,2836.77 h40
  text "DIO13" at 1734.97,2836.77 h40
  text "GND" at 1934.97,2836.77 h40
  text "GND" at 4438.23,2784.97 h40 r90
  text "GND" at 4695.24,2784.97 h40 r90
  text "GND" at 5925.73,2784.97 h40 r90
  text "GND" at 6182.74,2784.97 h40 r90
  text "GND" at 4409.97,2711.77 h40
  text "GND" at 5897.47,2711.77 h40
  text "VAUX" at 4438.23,2684.97 h40 r90
  text "VDDC" at 4737.74,2684.97 h40 r90
  text "VAUX" at 5925.73,2684.97 h40 r90
  text "VDDC" at 6225.24,2684.97 h40 r90
  text "3.3V" at 4438.23,2584.97 h40 r90
  text "VDDIO" at 4695.24,2584.97 h40 r90
  text "3.3V" at 5925.73,2584.97 h40 r90
  text "VDDIO" at 6182.74,2584.97 h40 r90
  text "DIO0" at 1134.98,2579.76 h40
  text "DIO4" at 1334.97,2579.76 h40
  text "DIO8" at 1534.97,2579.76 h40
  text "DIO12" at 1734.97,2579.76 h40
  text "GND" at 1934.97,2579.76 h40
  text "DIO2" at 1234.97,2537.26 h40
  text "DIO6" at 1434.97,2537.26 h40
  text "DIO10" at 1634.97,2537.26 h40
  text "DIO14" at 1834.97,2537.26 h40
  text "ALRM_OUT" at 4400.24,2484.97 h40 r90
  text "ALRM_IN" at 4737.74,2484.97 h40 r90
  text "ALRM_OUT" at 5887.74,2484.97 h40 r90
  text "ALRM_IN" at 6225.24,2484.97 h40 r90
  text "VBAT" at 4409.97,2454.76 h40
  text "VBAT" at 5897.47,2454.76 h40
  text "SDA" at 4438.23,2384.97 h40 r90
  text "SCL" at 4695.24,2384.97 h40 r90
  text "SDA" at 5925.73,2384.97 h40 r90
  text "SCL" at 6182.74,2384.97 h40 r90
  text "GPIO7" at 4400.24,2284.97 h40 r90
  text "GPIO6" at 4737.74,2284.97 h40 r90
  text "GPIO7" at 5887.74,2284.97 h40 r90
  text "GPIO6" at 6225.24,2284.97 h40 r90
  text "GPIO3" at 4438.23,2184.97 h40 r90
  text "GPIO2" at 4695.24,2184.97 h40 r90
  text "GPIO3" at 5925.73,2184.97 h40 r90
  text "GPIO2" at 6182.74,2184.97 h40 r90
  text "GND" at 4159.97,1711.77 h40
  text "VBAT_ext" at 4159.97,1454.76 h40
  text "Alarm / out" at 4674.34,594.9 h60
  text "Alarm / in" at 5824.34,594.88 h60
  text "TPL / low" at 5084.97,587.26 h60
  text "TPL / high" at 5459.97,587.26 h60
  text "GND" at 596.98,524.76 h40
  text "GND" at 714.97,524.76 h40
  text "GND" at 832.97,524.76 h40
  text "GND" at 950.96,524.76 h40
  text "GND" at 1068.99,524.76 h40
  text "GND" at 1186.98,524.76 h40
  text "GND" at 1304.97,524.76 h40
  text "GND" at 1422.97,524.76 h40
  text "GND" at 1746.98,524.76 h40
  text "GND" at 1864.97,524.76 h40
  text "GND" at 1982.97,524.76 h40
  text "GND" at 2100.96,524.76 h40
  text "GND" at 2218.99,524.76 h40
  text "GND" at 2336.98,524.76 h40
  text "GND" at 2454.97,524.76 h40
  text "GND" at 2572.97,524.76 h40
  text "NC" at 2905.49,524.76 h40
  text "NC" at 3023.99,524.76 h40
  text "NC" at 3141.98,524.76 h40
  text "NC" at 3259.97,524.76 h40
  text "CIN14" at 3377.97,524.76 h40
  text "CIN12" at 3495.96,524.76 h40
  text "CIN10" at 3613.99,524.76 h40
  text "CIN8" at 3731.98,524.76 h40
  text "CIN6" at 3849.97,524.76 h40
  text "CIN4" at 3967.97,524.76 h40
  text "CIN2" at 4085.96,524.76 h40
  text "CIN0" at 4204.46,524.76 h40
  text "N" at 4622.47,437.26 h60
  text "N" at 4902.78,437.26 h60
  text "N" at 5277.77,437.26 h60
  text "N" at 5652.77,437.26 h60
  text "P" at 4622.47,319.27 h60
  text "P" at 4902.21,318.51 h60
  text "P" at 5277.21,318.51 h60
  text "P" at 5652.21,318.51 h60
  text "T15" at 596.98,249.76 h60
  text "T14" at 714.97,249.76 h60
  text "T13" at 832.97,249.76 h60
  text "T12" at 950.96,249.76 h60
  text "T11" at 1068.99,249.76 h60
  text "T10" at 1186.98,249.76 h60
  text "T9" at 1304.97,249.76 h60
  text "T8" at 1422.97,249.76 h60
  text "T7" at 1746.98,249.76 h60
  text "T6" at 1864.97,249.76 h60
  text "T5" at 1982.97,249.76 h60
  text "T4" at 2100.96,249.76 h60
  text "T3" at 2218.99,249.76 h60
  text "T2" at 2336.98,249.76 h60
  text "T1" at 2454.97,249.76 h60
  text "T0" at 2572.97,249.76 h60
  text "NC" at 2905.49,249.76 h40
  text "NC" at 3023.99,249.76 h40
  text "NC" at 3141.98,249.76 h40
  text "VBAT" at 3259.97,249.76 h40
  text "CIN13" at 3377.97,249.76 h40
  text "CIN11" at 3495.96,249.76 h40
  text "CIN9" at 3613.99,249.76 h40
  text "CIN7" at 3731.98,249.76 h40
  text "CIN5" at 3849.97,249.76 h40
  text "CIN3" at 3967.97,249.76 h40
  text "CIN1" at 4085.96,249.76 h40
  text "GND" at 4204.46,249.76 h40
Mechanical 1:
  lines w78.74: 225,3100 775,3100 ; 700,2337.5 650,2287.5 387.5,2287.5 337.5,2337.5 337.5,2587.5 387.5,2637.5 650,2637.5 700,2587.5 ; 4787.5,100 4787.5,675 4625,837.5 4625,1350 5037.5,1350 ; 4812.5,1112.5 5237.5,1112.5 ; 5162.5,100 5162.5,875 5237.5,950 5237.5,962.5 5237.5,1350 5675,1350 ; 5450,1112.5 5875,1112.5 ; 5537.5,100 5537.5,612.5 5837.5,912.5 5837.5,1012.5 5875,1050 5875,1225 6025,1225 6025.77,1225 6095.79,1154.98 6129.98,1154.98 6187.5,1212.5 6200,1225 6200,1400 6150,1450
Board_Outline:
  the board outline again, w5.91

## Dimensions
6037.4,3740.16 to 5799.21,3740.16 on Board_Outline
